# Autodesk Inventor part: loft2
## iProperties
Shininess: 64.0
Length Units: 11269
Angle Units: 11279
Time Units: 11290
Mass Units: 11283
Length Display Precision: 3
Angle Display Precision: 2
Compacted: True
Part Number: loft2
Document SubType Name: Modeling
Created: 2002-12
Designer: deepak
Density: 1 g/cm^3
Density: 0.0
Volumn: 0.0
Area: 0.0
PropertySet Name: Model Information
Control State: 0
Master: False
Checked Out: False
Author: deepak
